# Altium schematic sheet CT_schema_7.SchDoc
size 254 x 245 mm
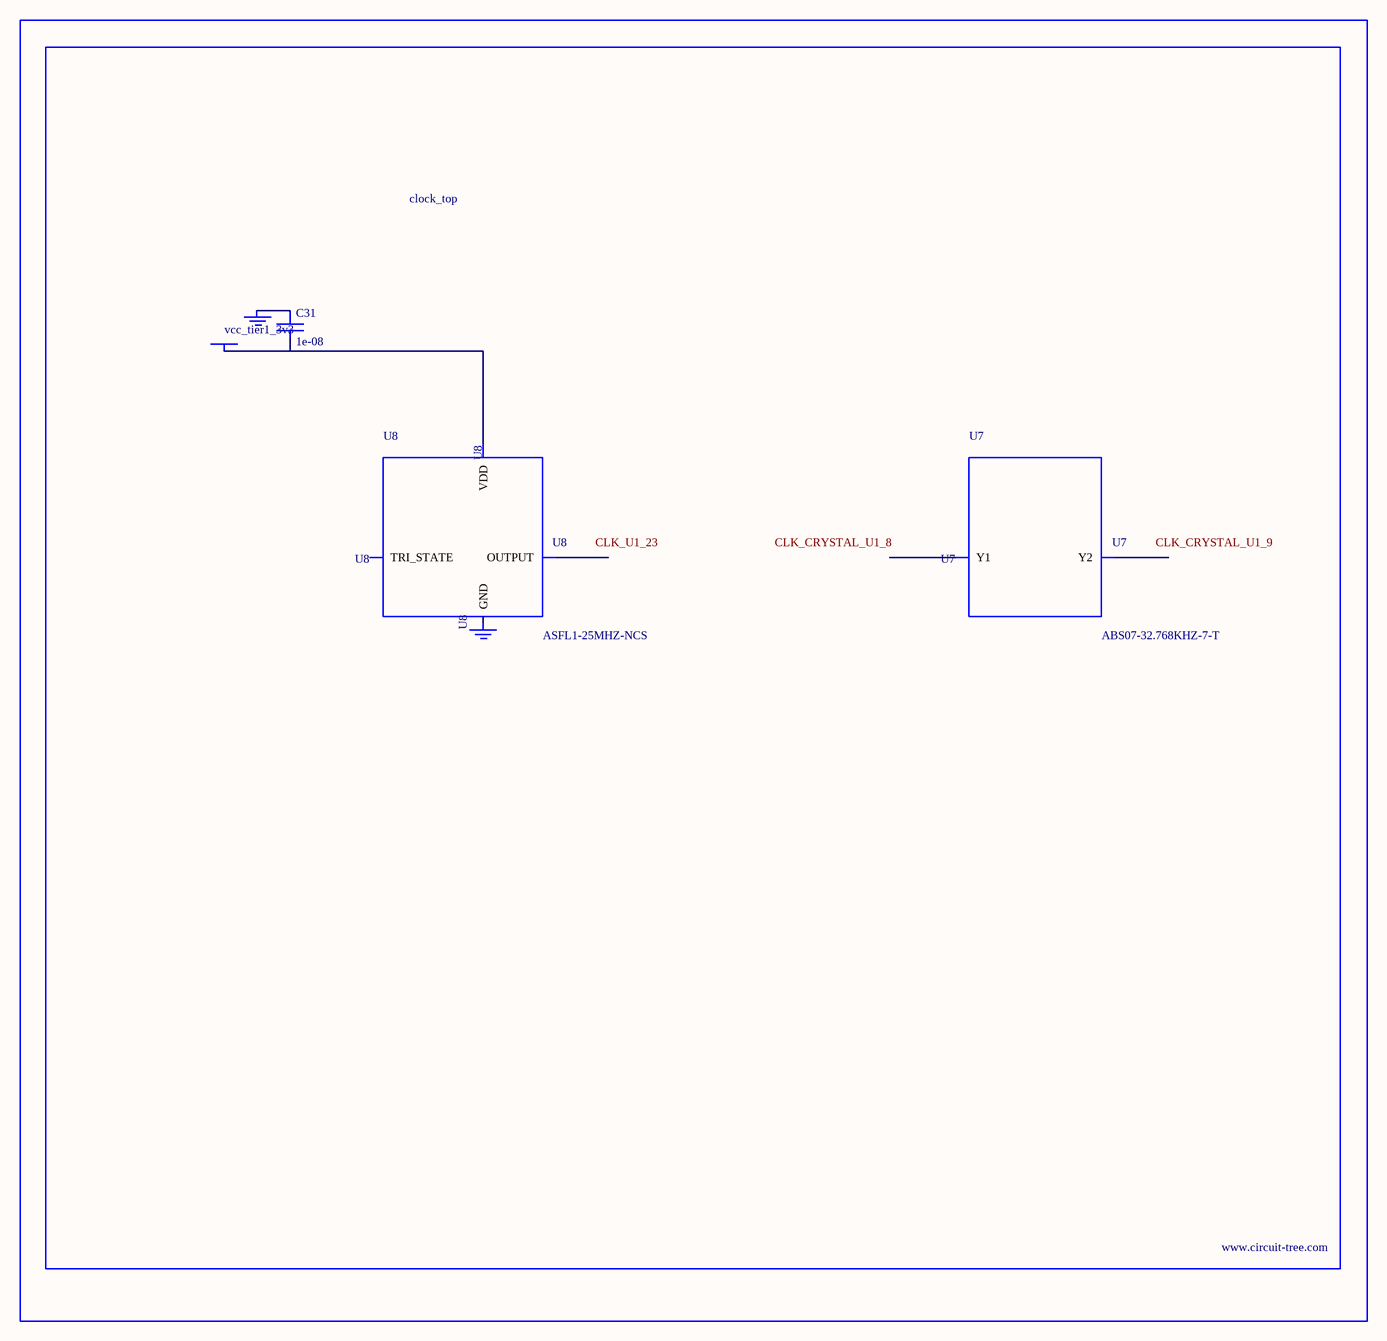
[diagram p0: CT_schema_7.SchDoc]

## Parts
BORDER6  (no value)
C31  1e-08  [C0402]
GND_INSTANCE_6_0  (no value)
GND_INSTANCE_6_1  (no value)
POWER_INSTANCE_6_0  vcc_tier1_3v3
U7  ABS07-32.768KHZ-7-T  [ABS07-32.768KHZ-7-T]
U8  ASFL1-25MHZ-NCS  [ASFL1]

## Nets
NetC31_1: C31.1 GND_INSTANCE_6_0.0(GND)
NetC31_2: C31.2 POWER_INSTANCE_6_0.0(PWR) U8.4(VDD)

Not connected (* = marked no-connect by the designer): GND_INSTANCE_6_1 0(GND); U7 1(Y1) 2(Y2); U8 1(TRI_STATE) 2(GND) 3(OUTPUT)

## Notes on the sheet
- Labels drawn without touching a wire or pin: CLK_CRYSTAL_U1_8, CLK_CRYSTAL_U1_9, CLK_U1_23

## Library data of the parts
BORDER6 = BORDER_PAGE6
C31 = C0402C103K3RAC
GND_INSTANCE_6_0 GND_INSTANCE_6_1 = GND
POWER_INSTANCE_6_0 = PWR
